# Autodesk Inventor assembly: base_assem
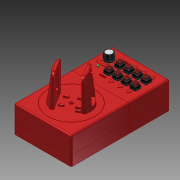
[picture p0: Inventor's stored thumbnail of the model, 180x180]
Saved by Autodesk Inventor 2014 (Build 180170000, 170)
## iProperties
Created: 2014-04
Part Number: base_assem
Document SubType Name: Assembly
Designer: t_emanb
Author: t_emanb
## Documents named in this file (14)
- C:\Users\t_emanb\Documents\3D printed arm\4th version\base_assem.iam
- C:\Users\t_emanb\Documents\3D printed arm\4th version\base_bottombuttonsBox.ipt
- C:\Users\t_emanb\Documents\3D printed arm\4th version\base_bottomrotateBox.ipt
- C:\Users\t_emanb\Documents\3D printed arm\4th version\base_topbuttonsBox.ipt
- C:\Users\t_emanb\Documents\3D printed arm\4th version\base_toprotateBox.ipt
- C:\Users\t_emanb\Documents\3D printed arm\4th version\base_bottomrotate.ipt
- C:\Users\t_emanb\Documents\3D printed arm\4th version\base_toprotate.ipt
- C:\Users\t_emanb\Documents\3D printed arm\stock parts\servo_assem.iam
- C:\Users\t_emanb\Documents\3D printed arm\stock parts\arduino_uno.ipt
- C:\Users\t_emanb\Documents\3D printed arm\stock parts\pushbutton_2751566.ipt
- C:\Users\t_emanb\Documents\3D printed arm\stock parts\led.ipt
- C:\Users\t_emanb\Documents\3D printed arm\4th version\base_servomountcurve.ipt
- C:\Users\t_emanb\Documents\3D printed arm\4th version\base_servomountcurveMirror.ipt
- C:\Users\t_emanb\Documents\3D printed arm\stock parts\knob_pot.ipt
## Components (20 placed, 13 different names)
1. base_bottombuttonsBox:1 — Flush:1, Mate:1, Flush:2, Flush:7, Mate:2
2. base_bottomrotateBox:1 — Flush:1, Mate:1, Flush:2, Flush:5, Flush:6, Mate:18
3. base_topbuttonsBox:1 — Flush:3, Flush:4, Flush:5, Flush:6, Mate:19, Mate:20, Mate:21, Mate:22, Mate:23, Mate:24, Mate:25, Mate:26, Mate:27, Mate:28, Mate:29, Mate:30, Mate:31, Mate:32, Mate:33, Mate:34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
4. base_toprotateBox:1 — Flush:3, Flush:4, Flush:7, Mate:2, Flush:8, Angle:1, Mate:49
5. base_bottomrotate:1 — Mate:5, Mate:13, Mate:14, Mate:50, Mate:51
6. base_toprotate:1 — Mate:5, Flush:8, Mate:15, Mate:41, Mate:42, Mate:43, Mate:44, Mate:45, Mate:46, Mate:49, Mate:50, Mate:51
7. servo_assem:1 [sub-assembly] — Mate:13, Mate:14, Mate:15, Angle:1
8. arduino_uno:1 — Mate:18
9. pushbutton_2751566:1 — Mate:19, Mate:31, Mate:32
10. pushbutton_2751566:2 — Mate:20, Mate:36, Mate:37, Mate:38
11. pushbutton_2751566:3 — Mate:21, Mate:26, Mate:28
12. pushbutton_2751566:4 — Mate:22, Mate:29, Mate:30
13. pushbutton_2751566:5 — Mate:23, Mate:33, Mate:34, Mate:35
14. pushbutton_2751566:6 — Mate:24, Mate:25, Mate:27
15. led:1 — Mate:39, Mate:40
16. base_servomountcurve:1 — Mate:41, Mate:42, Mate:43
17. base_servomountcurveMirror:1 — Mate:44, Mate:45, Mate:46
18. knob_pot:1 — Mate:47, Mate:48
19. pushbutton_2751566:7 — Mate:52, Mate:54, Mate:57
20. pushbutton_2751566:8 — Mate:53, Mate:55, Mate:56
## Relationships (55: Mate 46, Flush 8, Angle 1)
- Flush:1: base_bottombuttonsBox:1 ↔ base_bottomrotateBox:1
- Mate:1: base_bottombuttonsBox:1 ↔ base_bottomrotateBox:1
- Flush:2: base_bottombuttonsBox:1 ↔ base_bottomrotateBox:1
- Flush:3: base_topbuttonsBox:1 ↔ base_toprotateBox:1
- Flush:4: base_topbuttonsBox:1 ↔ base_toprotateBox:1
- Flush:5: base_bottomrotateBox:1 ↔ base_topbuttonsBox:1
- Flush:6: base_bottomrotateBox:1 ↔ base_topbuttonsBox:1
- Flush:7: base_bottombuttonsBox:1 ↔ base_toprotateBox:1
- Mate:2: base_bottombuttonsBox:1 ↔ base_toprotateBox:1
- Mate:5: base_bottomrotate:1 ↔ base_toprotate:1
- Flush:8: base_toprotateBox:1 ↔ base_toprotate:1
- Mate:13: base_bottomrotate:1 ↔ servo_assem:1
- Mate:14: base_bottomrotate:1 ↔ servo_assem:1
- Mate:15: base_toprotate:1 ↔ servo_assem:1
- Angle:1: base_toprotateBox:1 ↔ servo_assem:1
- Mate:18: base_bottomrotateBox:1 ↔ arduino_uno:1
- Mate:19: base_topbuttonsBox:1 ↔ pushbutton_2751566:1
- Mate:20: base_topbuttonsBox:1 ↔ pushbutton_2751566:2
- Mate:21: base_topbuttonsBox:1 ↔ pushbutton_2751566:3
- Mate:22: base_topbuttonsBox:1 ↔ pushbutton_2751566:4
- Mate:23: base_topbuttonsBox:1 ↔ pushbutton_2751566:5
- Mate:24: base_topbuttonsBox:1 ↔ pushbutton_2751566:6
- Mate:25: base_topbuttonsBox:1 ↔ pushbutton_2751566:6
- Mate:26: base_topbuttonsBox:1 ↔ pushbutton_2751566:3
- Mate:27: base_topbuttonsBox:1 ↔ pushbutton_2751566:6
- Mate:28: base_topbuttonsBox:1 ↔ pushbutton_2751566:3
- Mate:29: base_topbuttonsBox:1 ↔ pushbutton_2751566:4
- Mate:30: base_topbuttonsBox:1 ↔ pushbutton_2751566:4
- Mate:31: base_topbuttonsBox:1 ↔ pushbutton_2751566:1
- Mate:32: base_topbuttonsBox:1 ↔ pushbutton_2751566:1
- Mate:33: base_topbuttonsBox:1 ↔ pushbutton_2751566:5
- Mate:34: base_topbuttonsBox:1 ↔ pushbutton_2751566:5
- Mate:35: base_topbuttonsBox:1 ↔ pushbutton_2751566:5
- Mate:36: base_topbuttonsBox:1 ↔ pushbutton_2751566:2
- Mate:37: base_topbuttonsBox:1 ↔ pushbutton_2751566:2
- Mate:38: base_topbuttonsBox:1 ↔ pushbutton_2751566:2
- Mate:39: base_topbuttonsBox:1 ↔ led:1
- Mate:40: base_topbuttonsBox:1 ↔ led:1
- Mate:41: base_toprotate:1 ↔ base_servomountcurve:1
- Mate:42: base_toprotate:1 ↔ base_servomountcurve:1
- Mate:43: base_toprotate:1 ↔ base_servomountcurve:1
- Mate:44: base_toprotate:1 ↔ base_servomountcurveMirror:1
- Mate:45: base_toprotate:1 ↔ base_servomountcurveMirror:1
- Mate:46: base_toprotate:1 ↔ base_servomountcurveMirror:1
- Mate:47: base_topbuttonsBox:1 ↔ knob_pot:1
- Mate:48: base_topbuttonsBox:1 ↔ knob_pot:1
- Mate:49: base_toprotateBox:1 ↔ base_toprotate:1
- Mate:50: base_bottomrotate:1 ↔ base_toprotate:1
- Mate:51: base_bottomrotate:1 ↔ base_toprotate:1
- Mate:52: base_topbuttonsBox:1 ↔ pushbutton_2751566:7
- Mate:53: base_topbuttonsBox:1 ↔ pushbutton_2751566:8
- Mate:54: base_topbuttonsBox:1 ↔ pushbutton_2751566:7
- Mate:55: base_topbuttonsBox:1 ↔ pushbutton_2751566:8
- Mate:56: base_topbuttonsBox:1 ↔ pushbutton_2751566:8
- Mate:57: base_topbuttonsBox:1 ↔ pushbutton_2751566:7
